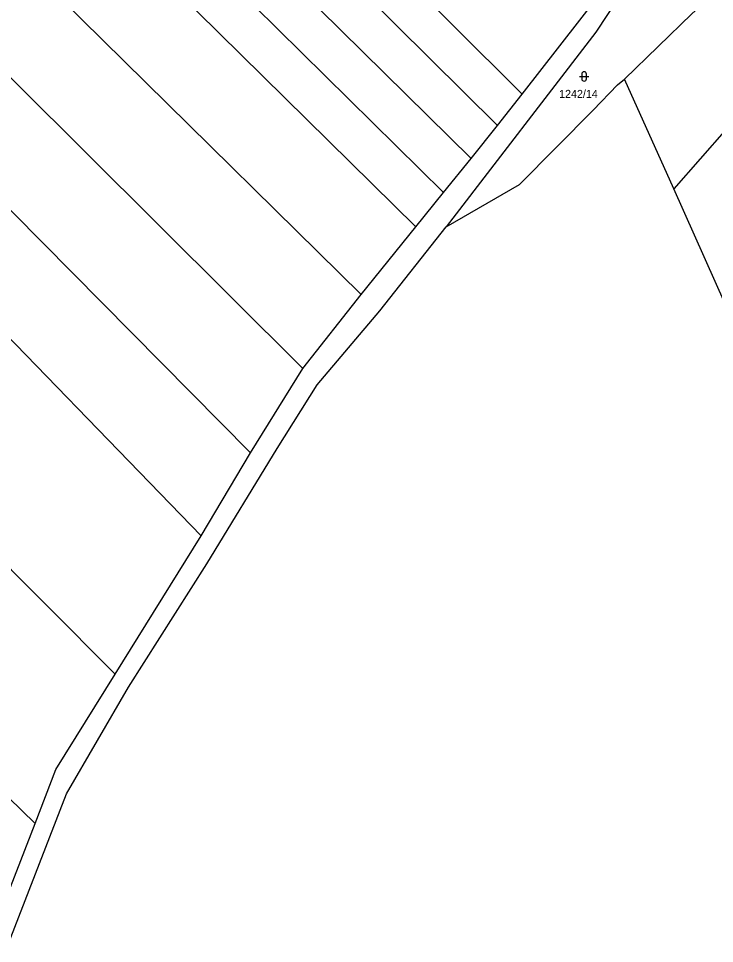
# Model space of a CAD drawing. Extents: x -755528 to -748832, y -1118122 to -1111095.
# Drawn here: x -751417.4 to -751269.6, y -1115414.6 to -1115218.2 of the extents above; entities that cross this region are included whole.
import ezdxf

# ---------------------------------------------------------------- set-up
doc = ezdxf.new("R2010")
doc.units = 0
for name, color, linetype in [('DZ_DO_PUPFL', 7, 'Continuous'), ('DZ_NAD_PUPFL', 7, 'Continuous'), ('DZ_NAD_ZPF', 7, 'Continuous'), ('TZ_UMVŽST', 7, 'Continuous')]:
    doc.layers.add(name, color=color, linetype=linetype)

msp = doc.modelspace()

# ---------------------------------------------------------------- linework, layer by layer
at = {"layer": 'DZ_NAD_PUPFL'}
for points in [[(-751288.73, -1115231.03), (-751274.37, -1115217.14), (-751272.13, -1115215.14)], [(-751288.73, -1115231.03), (-751274.37, -1115217.14), (-751272.13, -1115215.14)], [(-751326.55, -1115262.38), (-751311.03, -1115253.43), (-751295.37, -1115237.65), (-751290.19, -1115232.23), (-751288.73, -1115231.03)], [(-751326.55, -1115262.38), (-751311.03, -1115253.43), (-751295.37, -1115237.65), (-751290.19, -1115232.23), (-751288.73, -1115231.03)], [(-751362.51, -1115309.43), (-751353.99, -1115295.97), (-751340.69, -1115280.26), (-751326.55, -1115262.38)], [(-751362.51, -1115309.43), (-751353.99, -1115295.97), (-751340.69, -1115280.26), (-751326.55, -1115262.38)], [(-751419.54, -1115414.55), (-751407.22, -1115382.79), (-751394.04, -1115360.16), (-751377.4, -1115333.92), (-751362.51, -1115309.43)], [(-751419.54, -1115414.55), (-751407.22, -1115382.79), (-751394.04, -1115360.16), (-751377.4, -1115333.92), (-751362.51, -1115309.43)]]:
    msp.add_lwpolyline(points, dxfattribs=at)
at = {"layer": 'DZ_NAD_ZPF'}
for p, q in [((-751310.44, -1115234.21), (-751292.41, -1115211.12)), ((-751278.24, -1115254.34), (-751288.73, -1115231.03)), ((-751315.64, -1115240.86), (-751310.44, -1115234.21)), ((-751321.27, -1115247.86), (-751315.64, -1115240.86)), ((-751327.12, -1115255.1), (-751321.27, -1115247.86)), ((-751209.4, -1115408.62), (-751278.24, -1115254.34)), ((-751333.03, -1115262.42), (-751327.12, -1115255.1)), ((-751344.61, -1115276.77), (-751333.03, -1115262.42)), ((-751356.99, -1115292.44), (-751344.61, -1115276.77)), ((-751368.11, -1115310.4), (-751356.99, -1115292.44)), ((-751378.65, -1115327.98), (-751368.11, -1115310.4)), ((-751396.88, -1115357.36), (-751378.65, -1115327.98)), ((-751421.37, -1115408.28), (-751413.91, -1115389.05))]:
    msp.add_line(p, q, dxfattribs=at)
for points in [[(-751611.54, -1114934.25), (-751502.55, -1115042.84), (-751469.94, -1115075.32), (-751384.97, -1115159.96), (-751310.44, -1115234.21)], [(-751315.64, -1115240.86), (-751387.64, -1115169.64), (-751473.51, -1115084.72), (-751508.95, -1115049.67), (-751611.99, -1114947.76)], [(-751321.27, -1115247.86), (-751390.42, -1115179.72), (-751474.79, -1115096.57), (-751515.39, -1115056.55), (-751612.64, -1114960.72)], [(-751327.12, -1115255.1), (-751392.5, -1115190.64), (-751476.05, -1115108.27), (-751521.69, -1115063.28), (-751613.13, -1114973.12)], [(-751333.03, -1115262.42), (-751393.33, -1115202.94), (-751477.33, -1115120.08), (-751528.04, -1115070.06), (-751613.63, -1114985.63)], [(-751344.61, -1115276.77), (-751394.97, -1115227.23), (-751480.94, -1115142.65), (-751539.94, -1115084.61), (-751615.7, -1115010.07)], [(-751356.99, -1115292.44), (-751403.05, -1115246.66), (-751490.29, -1115159.94), (-751549.32, -1115101.27), (-751621.58, -1115029.44)], [(-751368.11, -1115310.4), (-751418.59, -1115259.37), (-751499.72, -1115177.37), (-751558.64, -1115117.82), (-751627.48, -1115048.25)], [(-751378.65, -1115327.98), (-751433.41, -1115271.49), (-751504.7, -1115197.94), (-751567.36, -1115133.3), (-751632.94, -1115065.66)], [(-751146.1, -1115096.52), (-751166.9, -1115122.31), (-751255.81, -1115228.83), (-751278.24, -1115254.34)], [(-751396.88, -1115357.36), (-751455.66, -1115298.4), (-751517.85, -1115236.02), (-751585.93, -1115167.72), (-751646.49, -1115106.97)], [(-751661.35, -1115148.11), (-751601.74, -1115206.16), (-751534.09, -1115272.02), (-751481.49, -1115323.24), (-751413.91, -1115389.05)], [(-751287.6, -1115210.14), (-751294.82, -1115221.1), (-751326.55, -1115262.38)], [(-751413.91, -1115389.05), (-751409.46, -1115377.6), (-751396.88, -1115357.36)]]:
    msp.add_lwpolyline(points, dxfattribs=at)
at = {"layer": 'TZ_UMVŽST'}
for p, q in [((-751298.281, -1115230.471), (-751296.279, -1115230.471)), ((-751297.781, -1115229.971), (-751297.781, -1115230.972)), ((-751296.779, -1115230.972), (-751296.779, -1115229.971))]:
    msp.add_line(p, q, dxfattribs=at)
for centre, start, end in [((-751297.28, -1115229.9709), 0, 180), ((-751297.28, -1115230.9709), 180, 359.987886)]:
    msp.add_arc(centre, 0.5, start, end, dxfattribs=at)

# ---------------------------------------------------------------- texts
at = {"layer": 'DZ_DO_PUPFL'}
msp.add_text('1242/14', height=1.7, dxfattribs=at).set_placement((-751302.586, -1115235.02))

doc.saveas('drawing.dxf')
